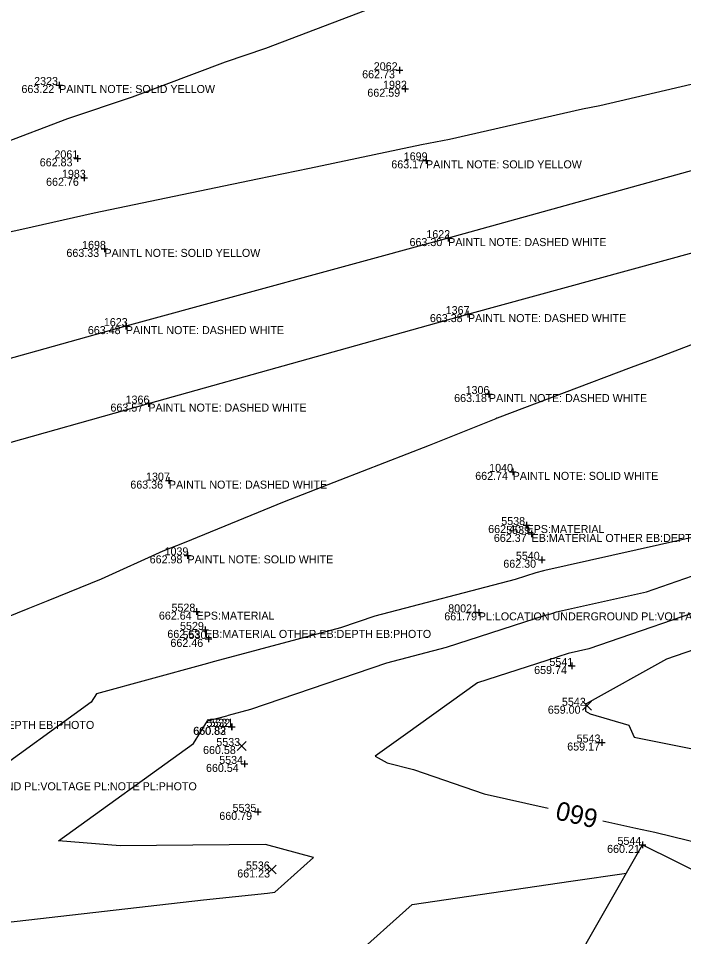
# Model space of a CAD drawing. Extents: x 2129350 to 2137777, y 657588 to 659885.
# Drawn here: x 2131480.3 to 2131580, y 658138.9 to 658276.6 of the extents above; entities that cross this region are included whole.
import ezdxf

# ---------------------------------------------------------------- set-up
doc = ezdxf.new("R2010")
doc.units = 0
for name, color, linetype in [('DT_X_Contour_Major', 7, 'Continuous'), ('DT_X_Contour_Minor', 7, 'Continuous'), ('DT_X_TIN_Hull', 7, 'Continuous'), ('PV_X_COP', 7, 'Continuous'), ('SV_X_Random_Point', 7, 'Continuous'), ('SV_X_Shot_Marker', 7, 'Continuous'), ('SV_X_Text_Comment', 7, 'Continuous'), ('SV_X_Text_Elevation', 7, 'Continuous'), ('SV_X_Text_Name', 7, 'Continuous')]:
    doc.layers.add(name, color=color, linetype=linetype)

msp = doc.modelspace()

# ---------------------------------------------------------------- linework, layer by layer
at = {"layer": 'DT_X_Contour_Major'}
for points in [[(2131600.72, 658192.33), (2131597.07, 658191.21), (2131586.11, 658189.03), (2131565.82, 658182.01), (2131562.7, 658181.31), (2131561.17, 658180.81), (2131561.04, 658180.78), (2131549.11, 658176.91), (2131538.33, 658169.16), (2131533.75, 658165.92), (2131535.58, 658164.91), (2131539.53, 658163.92), (2131550.1, 658160.26), (2131559.69, 658158.11)], [(2131567.87, 658156.22), (2131572.86, 658155.11), (2131575.71, 658154.54), (2131597.9, 658149.05), (2131598.9, 658147.77), (2131599.14, 658147.87), (2131618.53, 658143.43), (2131619.09, 658143.7), (2131625.62, 658142.54), (2131636.78, 658147.31)], [(2131495.66, 658124.79), (2131514.15, 658126.73), (2131521.21, 658127.47), (2131539.29, 658143.65), (2131563.11, 658147.15), (2131571.44, 658148.37)]]:
    msp.add_lwpolyline(points, dxfattribs=at)
at = {"layer": 'DT_X_Contour_Minor'}
for points in [[(2131534.83, 658278.71), (2131517.34, 658272.05), (2131511.27, 658269.97), (2131497.36, 658264.77), (2131487.66, 658261.49), (2131477.36, 658257.6)], [(2131467.19, 658242.02), (2131480.83, 658244.95), (2131491.64, 658247.4), (2131502.44, 658249.63), (2131516.15, 658252.51), (2131523.91, 658254.12), (2131540.69, 658257.65), (2131540.69, 658257.65), (2131544.89, 658258.44), (2131564.84, 658263.02), (2131567.44, 658263.52), (2131589.47, 658268.64)], [(2131589.68, 658230.83), (2131575.55, 658225.47), (2131572.14, 658224.2), (2131552.08, 658216.63), (2131551.99, 658216.59), (2131551.84, 658216.53), (2131541.84, 658212.52), (2131528.45, 658207.3), (2131520.11, 658204.05), (2131505.16, 658197.93), (2131501.95, 658196.66), (2131492.69, 658192.48), (2131484.7, 658189.21), (2131481.7, 658188.01), (2131466.69, 658181.9)], [(2131583.06, 658199.1), (2131559.19, 658193.77), (2131559.02, 658193.72), (2131557.86, 658193.42), (2131554.77, 658192.42), (2131533.73, 658186.9), (2131528.57, 658185.14), (2131509.69, 658180.12), (2131508.08, 658179.67), (2131492, 658175.26), (2131491.2, 658173.99), (2131475.29, 658162.5)], [(2131470.02, 658140.04), (2131508.03, 658144.39), (2131517.61, 658145.39), (2131518.73, 658145.51), (2131524.55, 658150.71), (2131517.35, 658152.69), (2131495.55, 658152.46), (2131486.31, 658153.23), (2131506.53, 658167.82), (2131508.66, 658171.19), (2131511.51, 658171.97), (2131511.8, 658172.05), (2131515.15, 658172.94), (2131535.53, 658179.9), (2131544.47, 658182.24), (2131559.45, 658187.1), (2131560.1, 658187.27), (2131560.95, 658187.54), (2131574.44, 658190.55), (2131584.78, 658194.14)], [(2131587.44, 658183.92), (2131577.42, 658180.46), (2131565.41, 658173.77), (2131565.33, 658173.74), (2131565.32, 658172.67), (2131566.01, 658172.26), (2131571.77, 658170.58), (2131572.57, 658168.76), (2131586.6, 658165.97)]]:
    msp.add_lwpolyline(points, dxfattribs=at)
at = {"layer": 'DT_X_TIN_Hull'}
msp.add_lwpolyline([(2131478.92, 658068.21), (2131503.79, 658070.83), (2131528.65, 658073.45), (2131573.86, 658152.61), (2131617.57, 658130.95), (2131669.63, 658175.29), (2131715.13, 658184.95), (2131768.27, 658182.72), (2131818.39, 658187.33), (2131898.11, 658161.24), (2131936.89, 658164.18)], dxfattribs=at)
at = {"layer": 'PV_X_COP'}
for points in [[(2132219.18, 658429.82), (2132171.04, 658416.39), (2132123.24, 658402.04), (2132074.74, 658389.73), (2132026.86, 658375.92), (2131978.48, 658362.52), (2131930.38, 658349.99), (2131881.84, 658336.47), (2131833.58, 658323.11), (2131785.59, 658310.04), (2131736.99, 658296.06), (2131689.31, 658282.66), (2131640.89, 658270.23), (2131593.04, 658256.99), (2131544.72, 658243.6), (2131496.4, 658230.41), (2131448.12, 658216.93)], [(2131451.49, 658205.21), (2131499.77, 658218.79), (2131547.68, 658232.21), (2131596.22, 658245.48), (2131644.19, 658258.61), (2131693.03, 658271.05), (2131740.4, 658284.7), (2131788.8, 658297.99), (2131837.2, 658311.72), (2131885.18, 658324.95), (2131933.63, 658338.43), (2131981.61, 658351.41), (2132029.82, 658365.04), (2132078.39, 658378.04), (2132126.27, 658391.57), (2132174.31, 658404.93), (2132222.67, 658417.74)]]:
    msp.add_lwpolyline(points, dxfattribs=at)
at = {"layer": 'SV_X_Random_Point'}
for p, q in [((2131564.86, 658172.81), (2131566.19, 658174.14)), ((2131564.86, 658174.14), (2131566.19, 658172.81)), ((2131513.08, 658166.77), (2131514.42, 658168.1)), ((2131513.08, 658168.1), (2131514.42, 658166.77)), ((2131517.6, 658148.26), (2131518.93, 658149.59)), ((2131517.6, 658149.59), (2131518.93, 658148.26))]:
    msp.add_line(p, q, dxfattribs=at)
at = {"layer": 'SV_X_Shot_Marker'}
for p, q in [((2131537.44, 658269.28), (2131537.44, 658268.28)), ((2131536.94, 658268.78), (2131537.94, 658268.78)), ((2131537.44, 658268.78), (2131537.44, 658268.78)), ((2131485.9, 658266.57), (2131486.9, 658266.57)), ((2131486.4, 658267.07), (2131486.4, 658266.07)), ((2131486.4, 658266.57), (2131486.4, 658266.57)), ((2131538.25, 658266.51), (2131538.25, 658265.51)), ((2131537.75, 658266.01), (2131538.75, 658266.01)), ((2131538.25, 658266.01), (2131538.25, 658266.01)), ((2131488.63, 658255.57), (2131489.63, 658255.57)), ((2131489.13, 658256.07), (2131489.13, 658255.07)), ((2131489.13, 658255.57), (2131489.13, 658255.57)), ((2131541.39, 658255.77), (2131541.39, 658254.77)), ((2131540.89, 658255.27), (2131541.89, 658255.27)), ((2131541.39, 658255.27), (2131541.39, 658255.27)), ((2131490.13, 658253.15), (2131490.13, 658252.15)), ((2131489.63, 658252.65), (2131490.63, 658252.65)), ((2131490.13, 658252.65), (2131490.13, 658252.65)), ((2131544.22, 658243.6), (2131545.22, 658243.6)), ((2131544.72, 658244.1), (2131544.72, 658243.1)), ((2131544.72, 658243.6), (2131544.72, 658243.6)), ((2131492.69, 658241.99), (2131493.69, 658241.99)), ((2131493.19, 658242.49), (2131493.19, 658241.49)), ((2131493.19, 658241.99), (2131493.19, 658241.99)), ((2131547.18, 658232.21), (2131548.18, 658232.21)), ((2131547.68, 658232.71), (2131547.68, 658231.71)), ((2131547.68, 658232.21), (2131547.68, 658232.21)), ((2131496.4, 658230.91), (2131496.4, 658229.91)), ((2131495.9, 658230.41), (2131496.9, 658230.41)), ((2131496.4, 658230.41), (2131496.4, 658230.41)), ((2131550.32, 658220.22), (2131551.32, 658220.22)), ((2131550.82, 658220.72), (2131550.82, 658219.72)), ((2131550.82, 658220.22), (2131550.82, 658220.22)), ((2131499.27, 658218.79), (2131500.27, 658218.79)), ((2131499.77, 658219.29), (2131499.77, 658218.29)), ((2131499.77, 658218.79), (2131499.77, 658218.79)), ((2131554.38, 658209.05), (2131554.38, 658208.05)), ((2131502.35, 658207.24), (2131503.35, 658207.24)), ((2131502.85, 658207.74), (2131502.85, 658206.74)), ((2131502.85, 658207.24), (2131502.85, 658207.24)), ((2131553.88, 658208.55), (2131554.88, 658208.55)), ((2131554.38, 658208.55), (2131554.38, 658208.55)), ((2131555.96, 658200.58), (2131556.96, 658200.58)), ((2131556.46, 658201.08), (2131556.46, 658200.08)), ((2131556.46, 658200.58), (2131556.46, 658200.58)), ((2131556.72, 658199.24), (2131557.72, 658199.24)), ((2131557.22, 658199.74), (2131557.22, 658198.74)), ((2131557.22, 658199.24), (2131557.22, 658199.24)), ((2131505.64, 658196.53), (2131505.64, 658195.53)), ((2131505.14, 658196.03), (2131506.14, 658196.03)), ((2131505.64, 658196.03), (2131505.64, 658196.03)), ((2131558.25, 658195.37), (2131559.25, 658195.37)), ((2131558.75, 658195.87), (2131558.75, 658194.87)), ((2131558.75, 658195.37), (2131558.75, 658195.37)), ((2131507, 658188.09), (2131507, 658187.09)), ((2131549.3, 658187.98), (2131549.3, 658186.98)), ((2131506.5, 658187.59), (2131507.5, 658187.59)), ((2131507, 658187.59), (2131507, 658187.59)), ((2131548.8, 658187.48), (2131549.8, 658187.48)), ((2131549.3, 658187.48), (2131549.3, 658187.48)), ((2131508.28, 658185.35), (2131508.28, 658184.35)), ((2131507.78, 658184.85), (2131508.78, 658184.85)), ((2131508.28, 658184.85), (2131508.28, 658184.85)), ((2131508.8, 658184), (2131508.8, 658183)), ((2131508.3, 658183.5), (2131509.3, 658183.5)), ((2131508.8, 658183.5), (2131508.8, 658183.5)), ((2131563.23, 658179.94), (2131563.23, 658178.94)), ((2131562.73, 658179.44), (2131563.73, 658179.44)), ((2131563.23, 658179.44), (2131563.23, 658179.44)), ((2131511.75, 658170.31), (2131512.75, 658170.31)), ((2131511.79, 658170.32), (2131512.79, 658170.32)), ((2131512.25, 658170.81), (2131512.25, 658169.81)), ((2131512.25, 658170.31), (2131512.25, 658170.31)), ((2131512.29, 658170.82), (2131512.29, 658169.82)), ((2131512.29, 658170.32), (2131512.29, 658170.32)), ((2131567.25, 658167.96), (2131568.25, 658167.96)), ((2131567.75, 658168.46), (2131567.75, 658167.46)), ((2131567.75, 658167.96), (2131567.75, 658167.96)), ((2131513.67, 658164.75), (2131514.67, 658164.75)), ((2131514.17, 658165.25), (2131514.17, 658164.25)), ((2131514.17, 658164.75), (2131514.17, 658164.75)), ((2131516.17, 658158.06), (2131516.17, 658157.06)), ((2131515.67, 658157.56), (2131516.67, 658157.56)), ((2131516.17, 658157.56), (2131516.17, 658157.56)), ((2131573.36, 658152.61), (2131574.36, 658152.61)), ((2131573.86, 658153.11), (2131573.86, 658152.11)), ((2131573.86, 658152.61), (2131573.86, 658152.61))]:
    msp.add_line(p, q, dxfattribs=at)

# ---------------------------------------------------------------- texts
at = {"layer": 'DT_X_Contour_Major'}
msp.add_text('660', height=2.8, rotation=167.003, dxfattribs=at).set_placement((2131567.36, 658157.8))
at = {"layer": 'SV_X_Text_Comment'}
for s, p in [('PAINTL NOTE: SOLID YELLOW', (2131486.4, 658265.37)), ('PAINTL NOTE: SOLID YELLOW', (2131541.39, 658254.07)), ('PAINTL NOTE: DASHED WHITE', (2131544.72, 658242.41)), ('PAINTL NOTE: SOLID YELLOW', (2131493.19, 658240.79)), ('PAINTL NOTE: DASHED WHITE', (2131547.68, 658231.01)), ('PAINTL NOTE: DASHED WHITE', (2131496.4, 658229.21)), ('PAINTL NOTE: DASHED WHITE', (2131550.82, 658219.02)), ('PAINTL NOTE: DASHED WHITE', (2131499.77, 658217.59)), ('PAINTL NOTE: DASHED WHITE', (2131502.85, 658206.04)), ('PAINTL NOTE: SOLID WHITE', (2131554.38, 658207.35)), ('EPS:MATERIAL', (2131556.46, 658199.38)), ('EB:MATERIAL OTHER EB:DEPTH EB:PHOTO', (2131557.22, 658198.04)), ('PAINTL NOTE: SOLID WHITE', (2131505.64, 658194.83)), ('EPS:MATERIAL', (2131507, 658186.39)), ('PL:LOCATION UNDERGROUND PL:VOLTAGE PL:NOTE PL:PHOTO', (2131549.3, 658186.28)), ('EB:MATERIAL OTHER EB:DEPTH EB:PHOTO', (2131508.28, 658183.65)), ('EB:MATERIAL OTHER EB:DEPTH EB:PHOTO', (2131457.78, 658170)), ('PL:LOCATION UNDERGROUND PL:VOLTAGE PL:NOTE PL:PHOTO', (2131456.83, 658160.8))]:
    msp.add_text(s, height=1.2, dxfattribs=at).set_placement(p)
at = {"layer": 'SV_X_Text_Elevation'}
for s, p in [('662.73', (2131531.82, 658267.58)), ('663.22', (2131480.75, 658265.37)), ('662.59', (2131532.6, 658264.81)), ('662.83', (2131483.49, 658254.37)), ('663.17', (2131536.19, 658254.07)), ('662.76', (2131484.44, 658251.45)), ('663.30', (2131538.92, 658242.41)), ('663.33', (2131487.49, 658240.79)), ('663.38', (2131541.97, 658231.01)), ('663.48', (2131490.7, 658229.21)), ('663.18', (2131545.61, 658219.02)), ('663.57', (2131494.09, 658217.59)), ('663.36', (2131497.07, 658206.04)), ('662.74', (2131548.77, 658207.35)), ('662.40', (2131550.71, 658199.38)), ('662.37', (2131551.56, 658198.04)), ('662.98', (2131499.97, 658194.83)), ('662.30', (2131552.98, 658194.17)), ('662.64', (2131501.35, 658186.39)), ('661.79', (2131544.13, 658186.28)), ('662.63', (2131502.62, 658183.65)), ('662.46', (2131503.08, 658182.3)), ('659.74', (2131557.6, 658178.24)), ('659.00', (2131559.65, 658172.28)), ('660.83', (2131506.48, 658169.11)), ('660.82', (2131506.53, 658169.12)), ('660.58', (2131507.97, 658166.24)), ('659.17', (2131562.56, 658166.76)), ('660.54', (2131508.41, 658163.55)), ('660.79', (2131510.41, 658156.36)), ('660.21', (2131568.54, 658151.41)), ('661.23', (2131513.1, 658147.72))]:
    msp.add_text(s, height=1.2, dxfattribs=at).set_placement(p)
at = {"layer": 'SV_X_Text_Name'}
for s, p in [('2062', (2131533.56, 658268.78)), ('2323', (2131482.65, 658266.57)), ('1982', (2131534.95, 658266.01)), ('2061', (2131485.69, 658255.57)), ('1699', (2131538.05, 658255.27)), ('1983', (2131486.82, 658252.65)), ('1622', (2131541.44, 658243.6)), ('1698', (2131489.84, 658241.99)), ('1367', (2131544.34, 658232.21)), ('1623', (2131493.1, 658230.41)), ('1306', (2131547.32, 658220.22)), ('1366', (2131496.36, 658218.79)), ('1040', (2131550.86, 658208.55)), ('1307', (2131499.42, 658207.24)), ('5538', (2131552.67, 658200.58)), ('5539', (2131553.42, 658199.24)), ('1039', (2131502.2, 658196.03)), ('5540', (2131554.86, 658195.37)), ('5528', (2131503.24, 658187.59)), ('80021', (2131544.72, 658187.48)), ('5529', (2131504.52, 658184.85)), ('5530', (2131504.91, 658183.5)), ('5541', (2131559.89, 658179.44)), ('5542', (2131561.76, 658173.47)), ('5532', (2131508.48, 658170.31)), ('5531', (2131508.94, 658170.32)), ('5543', (2131563.97, 658167.96)), ('5533', (2131509.96, 658167.44)), ('5534', (2131510.39, 658164.75)), ('5535', (2131512.39, 658157.56)), ('5544', (2131570.09, 658152.61)), ('5536', (2131514.4, 658148.92))]:
    msp.add_text(s, height=1.2, dxfattribs=at).set_placement(p)

doc.saveas('drawing.dxf')
